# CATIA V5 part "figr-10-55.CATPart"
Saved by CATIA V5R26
Part number: Part1
Bounding box of the stored display mesh (mm): x -101.896 to 127.212, y -67.72 to 67.298, z 0 to 0
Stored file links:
  D:\_Deepak\CATIA\CATIA V5 2015 Parts Files\Part files\Partfiles\c10_catia_v5_6r2016_prt\figr-10-55.CATPart
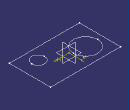
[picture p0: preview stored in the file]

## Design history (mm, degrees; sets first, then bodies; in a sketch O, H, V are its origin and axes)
Body1 (main body)
  Sketch1 on xy-plane, origin (0, 0, 0), H (1, 0, 0), V (0, 1, 0)
    line L1 (-101.8963, 67.298) -> (127.2122, 67.298)
    line L2 (127.2122, 67.298) -> (127.2122, -67.7199)
    line L3 (127.2122, -67.7199) -> (-101.8963, -67.7199)
    line L4 (-101.8963, -67.7199) -> (-101.8963, 67.298)
    horizontal: L1 H, L3 H
    vertical: L2 V, L4 V
  Sketch2 on xy-plane, origin (0, 0, 0), H (1, 0, 0), V (0, 1, 0)
    circle A1 centre (-45.2964, 9.2296) radius 39.3004
    circle A2 centre (71.0804, -29.9585) radius 20.9926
